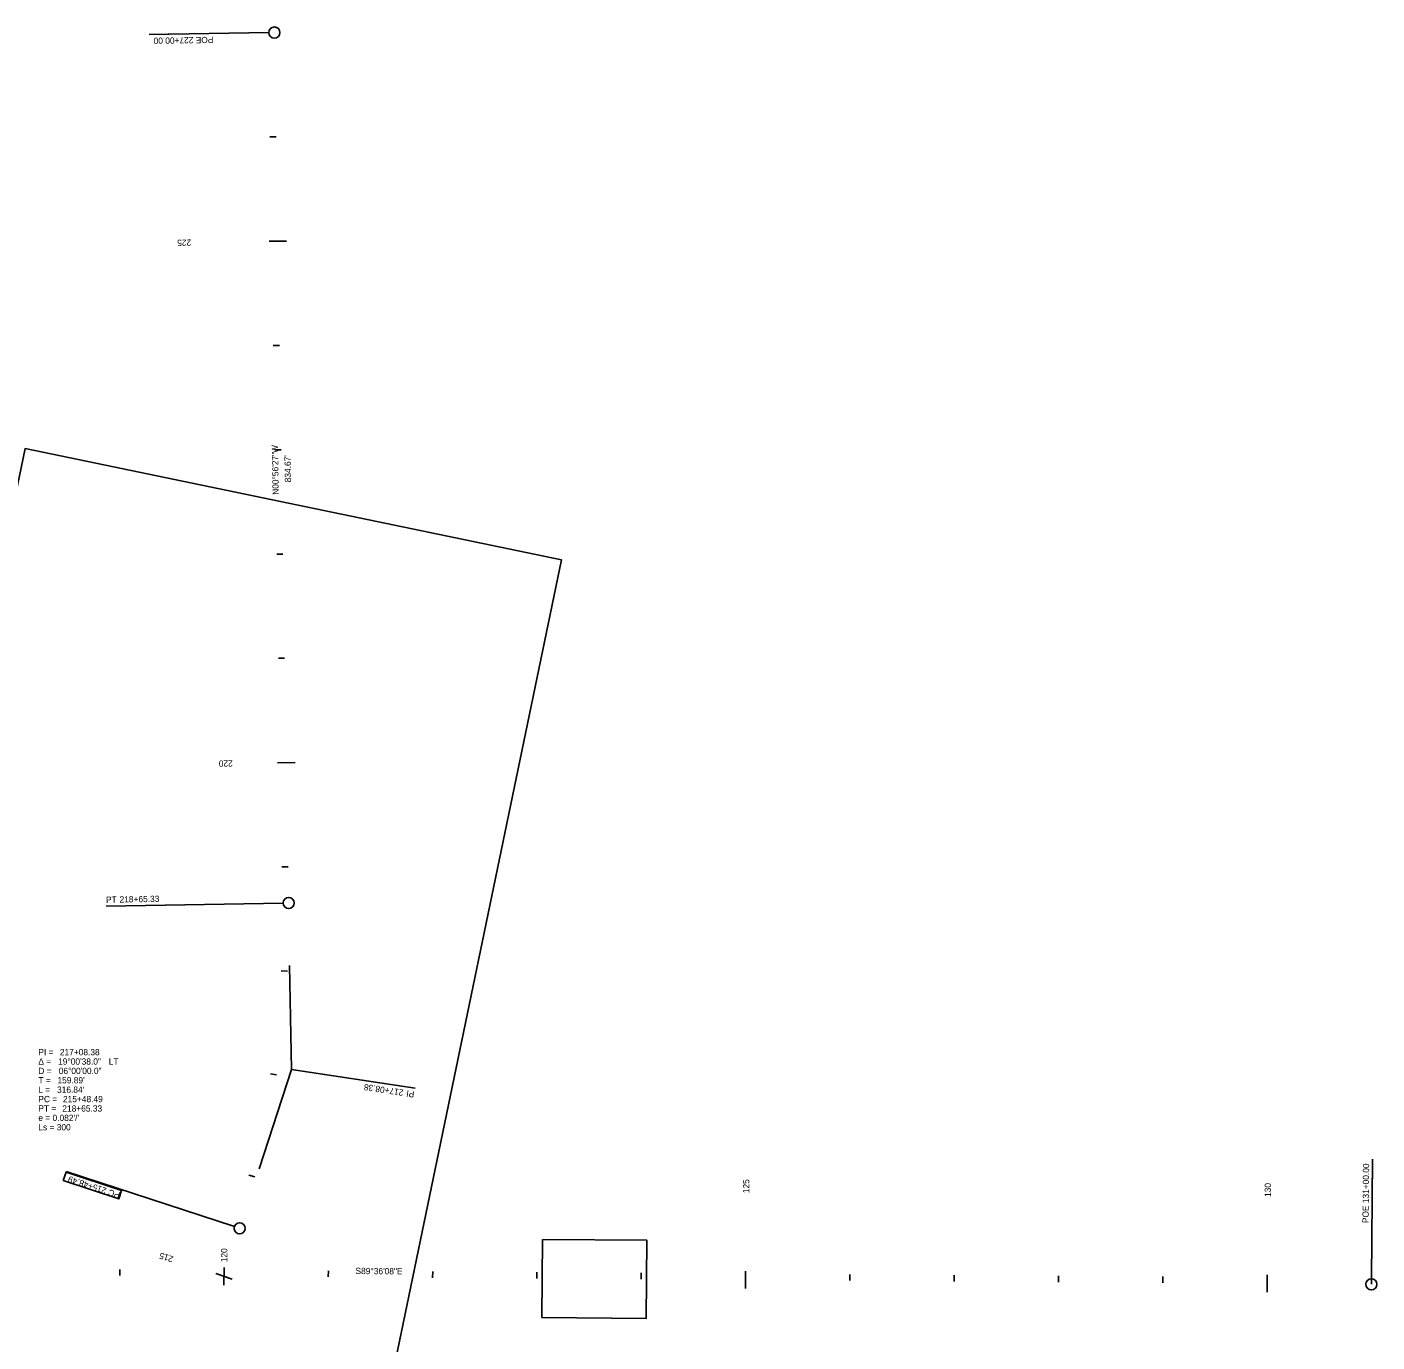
# Model space of a CAD drawing. Extents: x 1802364 to 1804577, y 572742 to 575010.
# Drawn here: x 1803283 to 1804577, y 573749 to 575010 of the extents above; entities that cross this region are included whole.
import ezdxf

# ---------------------------------------------------------------- set-up
doc = ezdxf.new("R2010")
doc.units = 0
for name, color, linetype in [('_CIVIL_CONSTRUCTION', 7, 'Continuous'), ('MOD_COR', 7, 'Continuous'), ('MOD_Edge of Pavement', 7, 'Continuous'), ('MOD_Points', 7, 'Continuous')]:
    doc.layers.add(name, color=color, linetype=linetype)

msp = doc.modelspace()

# ---------------------------------------------------------------- linework, layer by layer
at = {"layer": '_CIVIL_CONSTRUCTION'}
for p, q in [((1803515.1, 575004.8), (1803400.5, 575002.9)), ((1803400.5, 575002.9), (1803436.5, 575003.5)), ((1803520.5, 575004.9), (1803520.5, 575004.9)), ((1803516.1, 574904.8), (1803522.1, 574904.9)), ((1803515.3, 574804.8), (1803532.1, 574805)), ((1803519.4, 574704.8), (1803525.4, 574704.9)), ((1803521, 574604.8), (1803527, 574604.9)), ((1803522.7, 574504.8), (1803528.7, 574504.9)), ((1803524.3, 574404.9), (1803530.3, 574405)), ((1803523.5, 574304.8), (1803540.3, 574305.1)), ((1803527.6, 574204.9), (1803533.6, 574205)), ((1803528.8, 574170.2), (1803359.2, 574167.4)), ((1803359.2, 574167.4), (1803359.2, 574167.4)), ((1803534.2, 574170.3), (1803534.2, 574170.3)), ((1803527, 574105.3), (1803533, 574105)), ((1803536.8, 574010.5), (1803535.1, 574110.4)), ((1803536.8, 574010.5), (1803505.8, 573915.4)), ((1803516.7, 574006.5), (1803522.6, 574005.6)), ((1803536.8, 574010.5), (1803655.4, 573992.6)), ((1803655.4, 573992.6), (1803655.4, 573992.6)), ((1804572.2, 573810), (1804573, 573924.7)), ((1804573, 573924.7), (1804572.7, 573888.7)), ((1803320.8, 573912.7), (1803320.8, 573912.7)), ((1803482.1, 573860.1), (1803320.8, 573912.7)), ((1803496, 573909.4), (1803501.8, 573907.8)), ((1803487.2, 573858.4), (1803487.2, 573858.4)), ((1803372.2, 573819), (1803372.2, 573813)), ((1803472.2, 573820.7), (1803472.1, 573803.9)), ((1803572.2, 573817.7), (1803572.1, 573811.7)), ((1803672.2, 573817), (1803672.1, 573811)), ((1803972.2, 573817.3), (1803972.1, 573800.5)), ((1803464.2, 573815), (1803480.1, 573809.7)), ((1803772.2, 573816.3), (1803772.1, 573810.3)), ((1803872.2, 573815.6), (1803872.1, 573809.6)), ((1804072.2, 573814.2), (1804072.1, 573808.2)), ((1804172.2, 573813.5), (1804172.1, 573807.5)), ((1804272.2, 573812.8), (1804272.1, 573806.8)), ((1804372.2, 573812.1), (1804372.1, 573806.1)), ((1804472.2, 573813.8), (1804472.1, 573797)), ((1804572.2, 573810.7), (1804572.1, 573804.7)), ((1804572.1, 573804.7), (1804572.1, 573804.7))]:
    msp.add_line(p, q, dxfattribs=at)
msp.add_lwpolyline([(1803318, 573904.2), (1803371.3, 573886.5), (1803374, 573894.6), (1803320.7, 573912.3)], close=True, dxfattribs=at)
for centre in [(1803520.5, 575004.9), (1803534.2, 574170.3), (1803487.2, 573858.4), (1804572.1, 573804.7)]:
    msp.add_circle(centre, 5.34, dxfattribs=at)
at = {"layer": 'MOD_COR'}
msp.add_lwpolyline([(1802960.1, 573055.2), (1803474.1, 572948.6), (1803795.6, 574499.4), (1803281.5, 574606)], close=True, dxfattribs=at)
at = {"layer": 'MOD_Edge of Pavement'}
msp.add_lwpolyline([(1803777.4, 573847.7), (1803877.4, 573847), (1803876.9, 573772), (1803776.9, 573772.7)], close=True, dxfattribs=at)

# ---------------------------------------------------------------- texts
at = {"layer": '_CIVIL_CONSTRUCTION'}
for s, rotation, p in [('227+00.00', 180.9408, (1803442.8, 575000.6)), ('POE ', 180.9408, (1803461.9, 575000.9)), ('225', 180.9408, (1803440.6, 574806.5)), ('N00°56\'27"W', 90.9408, (1803524.7, 574561.7)), ('220', 180.9408, (1803480.5, 574307.1)), ('PT', 0.9408, (1803359.1, 574170.4)), ('218+65.33', 0.9408, (1803372.1, 574170.7)), ('217+08.38', 171.4356, (1803644.5, 573991.2)), ('PI ', 171.4356, (1803655, 573989.6)), ('215+48.49', 161.9303, (1803360.1, 573896.8)), ('131+00.00', 89.6021, (1804569.7, 573882.4)), ('PC', 161.9303, (1803373, 573892.5)), ('125', 89.6021, (1803975.7, 573892)), ('130', 89.6021, (1804475.7, 573888.4)), ('POE ', 89.6021, (1804569.5, 573863.3)), ('215', 161.9303, (1803424.1, 573831.2)), ('120', 89.6021, (1803475.2, 573825.8)), ('S89°36\'08"E', 359.6021, (1803598.2, 573814.5))]:
    msp.add_text(s, height=6, rotation=rotation, dxfattribs=at).set_placement(p)
for s, p in [('PI = ', (1803294.2, 574024.3)), ('217+08.38', (1803314.8, 574024.3)), ('Δ = ', (1803294.2, 574015.3)), ('D = ', (1803294.2, 574006.3)), ('19°00\'38.0"', (1803313.1, 574015.3)), ('06°00\'00.0"', (1803313.7, 574006.3)), (' LT', (1803359.4, 574015.3)), ('T = ', (1803294.2, 573997.3)), ("159.89'", (1803312.5, 573997.3)), ('L = ', (1803294.2, 573988.3)), ('PC = ', (1803294.2, 573979.3)), ("316.84'", (1803312.1, 573988.3)), ('215+48.49', (1803317.8, 573979.3)), ('PT = ', (1803294.2, 573970.3)), ('218+65.33', (1803317.2, 573970.3)), ("e = 0.082'/'", (1803294.2, 573961.3)), ('Ls = 300', (1803294.2, 573952.3))]:
    msp.add_text(s, height=6, dxfattribs=at).set_placement(p)
at = {"layer": 'MOD_Points'}
msp.add_text("834.67'", height=6, rotation=90.9408, dxfattribs=at).set_placement((1803536.5, 574573.7))

doc.saveas('drawing.dxf')
